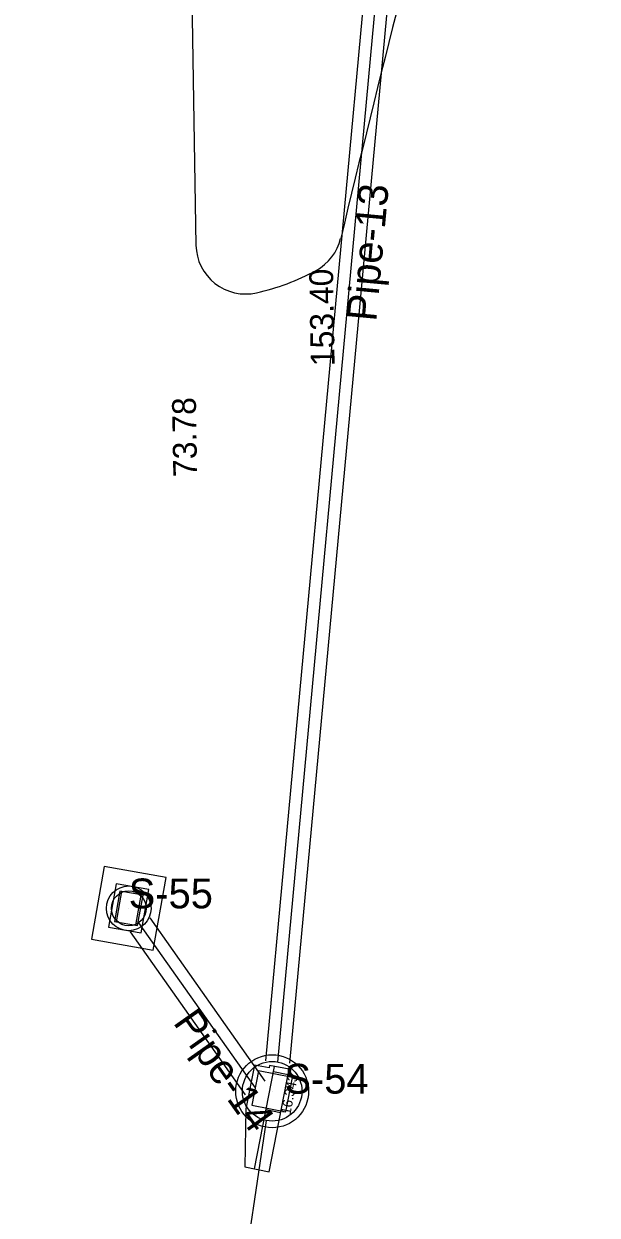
# Model space of a CAD drawing. Extents: x 925371 to 925937, y 853654 to 858024.
# Drawn here: x 925759.3 to 925817, y 857749.9 to 857869.8 of the extents above; entities that cross this region are included whole.
import ezdxf

# ---------------------------------------------------------------- set-up
doc = ezdxf.new("R2010")
doc.units = 0
for name, color, linetype in [('GPKDrBack_dp', 7, 'Continuous'), ('GPKDrBottom_dp', 7, 'Continuous'), ('GPKDrCellIns_dp', 7, 'Continuous'), ('GPKDrCentroid_dp', 7, 'Continuous'), ('GPKDrFront_dp', 7, 'Continuous'), ('GPKDrPipe_dp', 7, 'Continuous'), ('GPKDrPipeCir_dp', 7, 'Continuous'), ('InletBottomJ', 7, 'Continuous'), ('InletBottomP', 7, 'Continuous'), ('InletCurb', 7, 'Continuous'), ('InletDBI', 7, 'Continuous'), ('NonPlottingEle_dp', 7, 'Continuous'), ('PipeCulvert', 7, 'Continuous'), ('RetentionArea', 7, 'Continuous'), ('Scratch1_dp', 7, 'Continuous')]:
    doc.layers.add(name, color=color, linetype=linetype)

msp = doc.modelspace()

# ---------------------------------------------------------------- linework, layer by layer
at = {"layer": 'GPKDrBack_dp'}
for p, q in [((925768.14, 857781.04), (925768.14, 857781.04)), ((925768.22, 857781.02), (925768.22, 857781.02)), ((925781.35, 857762.9), (925781.35, 857762.9)), ((925782.09, 857762.76), (925782.09, 857762.76))]:
    msp.add_line(p, q, dxfattribs=at)
at = {"layer": 'GPKDrBottom_dp'}
for p, q in [((925768.86, 857782.17), (925768.86, 857782.17)), ((925769.14, 857782.43), (925769.14, 857782.43)), ((925770.13, 857782.25), (925770.13, 857782.25)), ((925770.16, 857782.46), (925770.16, 857782.46)), ((925771.11, 857782.08), (925771.11, 857782.08)), ((925768.14, 857781.04), (925768.14, 857781.04)), ((925768.88, 857780.91), (925768.88, 857780.91)), ((925769.86, 857780.74), (925769.86, 857780.74)), ((925769.86, 857780.74), (925769.86, 857780.74)), ((925771.29, 857781.74), (925771.29, 857781.74)), ((925768.43, 857779.73), (925768.43, 857779.73)), ((925770.85, 857780.56), (925770.85, 857780.56)), ((925771.58, 857780.43), (925771.58, 857780.43)), ((925768.61, 857779.39), (925768.61, 857779.39)), ((925769.56, 857779.01), (925769.56, 857779.01)), ((925769.59, 857779.22), (925769.59, 857779.22)), ((925770.58, 857779.04), (925770.58, 857779.04)), ((925770.86, 857779.3), (925770.86, 857779.3)), ((925784.87, 857765.27), (925784.87, 857765.27)), ((925782.62, 857764.81), (925782.62, 857764.81)), ((925782.92, 857764.38), (925782.92, 857764.38)), ((925784.63, 857764.04), (925784.63, 857764.04)), ((925786.79, 857764), (925786.79, 857764)), ((925781.35, 857762.9), (925781.35, 857762.9)), ((925782.58, 857762.66), (925782.58, 857762.66)), ((925786.35, 857763.71), (925786.35, 857763.71)), ((925784.3, 857762.33), (925784.3, 857762.33)), ((925784.3, 857762.33), (925784.3, 857762.33)), ((925786.02, 857761.99), (925786.02, 857761.99)), ((925787.24, 857761.75), (925787.24, 857761.75)), ((925781.81, 857760.65), (925781.81, 857760.65)), ((925782.25, 857760.94), (925782.25, 857760.94)), ((925783.97, 857760.61), (925783.97, 857760.61)), ((925785.68, 857760.27), (925785.68, 857760.27)), ((925783.73, 857759.38), (925783.73, 857759.38)), ((925785.98, 857759.84), (925785.98, 857759.84))]:
    msp.add_line(p, q, dxfattribs=at)
at = {"layer": 'GPKDrCellIns_dp'}
for p, q in [((925769.86, 857780.74), (925769.86, 857780.74)), ((925769.86, 857780.74), (925769.86, 857780.74)), ((925784.3, 857762.33), (925784.3, 857762.33)), ((925785.53, 857762.09), (925785.53, 857762.09))]:
    msp.add_line(p, q, dxfattribs=at)
at = {"layer": 'GPKDrCentroid_dp'}
msp.add_line((925784.3, 857762.33), (925784.3, 857762.33), dxfattribs=at)
msp.add_line((925784.3, 857762.33), (925784.3, 857762.33), dxfattribs=at)
at = {"layer": 'GPKDrFront_dp'}
for p, q in [((925771.5, 857780.45), (925771.5, 857780.45)), ((925771.58, 857780.43), (925771.58, 857780.43)), ((925785.53, 857762.09), (925785.53, 857762.09)), ((925787.24, 857761.75), (925787.24, 857761.75))]:
    msp.add_line(p, q, dxfattribs=at)
at = {"layer": 'GPKDrPipe_dp'}
for p, q in [((925768.88, 857782.18), (925768.88, 857782.18)), ((925769.49, 857782.45), (925769.49, 857782.45)), ((925770.13, 857782.25), (925770.13, 857782.25)), ((925770.16, 857782.46), (925770.16, 857782.46)), ((925770.83, 857782.19), (925770.83, 857782.19)), ((925768.14, 857781.04), (925768.14, 857781.04)), ((925768.41, 857781.71), (925768.41, 857781.71)), ((925768.88, 857780.91), (925768.88, 857780.91)), ((925771.31, 857781.72), (925771.31, 857781.72)), ((925771.57, 857781.1), (925771.57, 857781.1)), ((925768.15, 857780.37), (925768.15, 857780.37)), ((925768.41, 857779.75), (925768.41, 857779.75)), ((925770.85, 857780.56), (925770.85, 857780.56)), ((925771.32, 857779.76), (925771.32, 857779.76)), ((925771.58, 857780.43), (925771.58, 857780.43)), ((925768.89, 857779.28), (925768.89, 857779.28)), ((925769.56, 857779.01), (925769.56, 857779.01)), ((925769.59, 857779.22), (925769.59, 857779.22)), ((925770.23, 857779.02), (925770.23, 857779.02)), ((925770.84, 857779.29), (925770.84, 857779.29)), ((925783.72, 857765.27), (925783.72, 857765.27)), ((925784.87, 857765.27), (925784.87, 857765.27)), ((925781.83, 857764.04), (925781.83, 857764.04)), ((925782.66, 857764.84), (925782.66, 857764.84)), ((925784.63, 857764.04), (925784.63, 857764.04)), ((925786.01, 857764.79), (925786.01, 857764.79)), ((925786.81, 857763.97), (925786.81, 857763.97)), ((925781.35, 857762.9), (925781.35, 857762.9)), ((925782.58, 857762.66), (925782.58, 857762.66)), ((925787.24, 857762.9), (925787.24, 857762.9)), ((925781.36, 857761.75), (925781.36, 857761.75)), ((925786.02, 857761.99), (925786.02, 857761.99)), ((925787.24, 857761.75), (925787.24, 857761.75)), ((925781.79, 857760.68), (925781.79, 857760.68)), ((925783.97, 857760.61), (925783.97, 857760.61)), ((925786.76, 857760.62), (925786.76, 857760.62)), ((925782.59, 857759.86), (925782.59, 857759.86)), ((925783.73, 857759.38), (925783.73, 857759.38)), ((925784.88, 857759.38), (925784.88, 857759.38)), ((925785.94, 857759.81), (925785.94, 857759.81))]:
    msp.add_line(p, q, dxfattribs=at)
at = {"layer": 'GPKDrPipeCir_dp'}
msp.add_lwpolyline([(925785.68, 857760.27), (925786.35, 857763.71), (925782.92, 857764.38), (925782.25, 857760.94)], close=True, dxfattribs=at)
for centre, radius in [((925769.86, 857780.74), 1.75), ((925784.3, 857762.33), 3)]:
    msp.add_circle(centre, radius, dxfattribs=at)
at = {"layer": 'InletBottomJ'}
for radius in [3.67, 3]:
    msp.add_circle((925784.3, 857762.33), radius, dxfattribs=at)
at = {"layer": 'InletBottomP'}
for radius in [2.25, 1.75]:
    msp.add_circle((925769.86, 857780.74), radius, dxfattribs=at)
at = {"layer": 'InletCurb'}
for p, q in [((925782.52, 857764.96), (925781.66, 857760.55)), ((925783.99, 857764.68), (925782.52, 857764.96)), ((925782.53, 857754.52), (925784.53, 857764.83)), ((925784.04, 857764.92), (925783.99, 857764.68)), ((925784, 857754.23), (925786, 857764.54)), ((925786, 857764.54), (925784.04, 857764.92)), ((925785.9, 857764), (925784.43, 857764.29)), ((925781.66, 857760.55), (925781.55, 857754.71)), ((925785.15, 857760.17), (925783.68, 857760.45)), ((925781.55, 857754.71), (925784, 857754.23))]:
    msp.add_line(p, q, dxfattribs=at)
at = {"layer": 'InletDBI'}
for p, q in [((925767.39, 857784.94), (925766.1, 857777.63)), ((925773.62, 857783.84), (925767.39, 857784.94)), ((925768.6, 857783.2), (925767.84, 857778.85)), ((925771.89, 857782.62), (925768.6, 857783.2)), ((925772.33, 857776.53), (925773.62, 857783.84)), ((925768.96, 857782.46), (925768.42, 857779.42)), ((925769.14, 857782.43), (925768.61, 857779.39)), ((925771.3, 857782.05), (925768.96, 857782.46)), ((925770.58, 857779.04), (925771.11, 857782.08)), ((925770.76, 857779.01), (925771.3, 857782.05)), ((925771.12, 857778.27), (925771.89, 857782.62)), ((925767.84, 857778.85), (925771.12, 857778.27)), ((925768.42, 857779.42), (925770.76, 857779.01)), ((925766.1, 857777.63), (925772.33, 857776.53))]:
    msp.add_line(p, q, dxfattribs=at)
at = {"layer": 'PipeCulvert'}
for p, q in [((925784.87, 857765.27), (925798.7, 857914.78)), ((925770.84, 857779.29), (925782.58, 857762.66)), ((925759.3, 857596.06), (925783.73, 857759.38))]:
    msp.add_line(p, q, dxfattribs=at)
at = {"layer": 'RetentionArea'}
msp.add_line((925774.33, 857985.16), (925776.63, 857847.49), dxfattribs=at)
for centre, radius, start, end in [((927701.56, 857389.08), 1964.75, 163.57215, 166.48718), ((925786.33, 857849.34), 5, 298.453, 346.4872), ((925781.63, 857847.57), 5, 180.9573, 282.626), ((925777.64, 857865.38), 23.25, 282.626, 298.453)]:
    msp.add_arc(centre, radius, start, end, dxfattribs=at)
at = {"layer": 'Scratch1_dp'}
for p, q in [((925783.67, 857765.38), (925797.49, 857914.89)), ((925786.07, 857765.16), (925799.9, 857914.66)), ((925771.97, 857779.78), (925783.57, 857763.36)), ((925770, 857778.38), (925781.59, 857761.96))]:
    msp.add_line(p, q, dxfattribs=at)

# ---------------------------------------------------------------- texts
at = {"layer": 'NonPlottingEle_dp'}
for s, height, rotation, p in [('Pipe-13', 3, 84.7169, (925794.77, 857839.75)), ('153.40', 2.4, 90.9741, (925790.59, 857835.33)), ('73.78', 2.4, 90.9741, (925776.75, 857824.17)), ('Pipe-14', 3, 305.2202, (925774.26, 857769.24)), ('16.343', 1, 79.0428, (925786.13, 857759.92))]:
    msp.add_text(s, height=height, rotation=rotation, dxfattribs=at).set_placement(p)
for s, p in [('S-55', (925769.86, 857780.74)), ('S-54', (925785.53, 857762.09))]:
    msp.add_text(s, height=3, dxfattribs=at).set_placement(p)

doc.saveas('drawing.dxf')
